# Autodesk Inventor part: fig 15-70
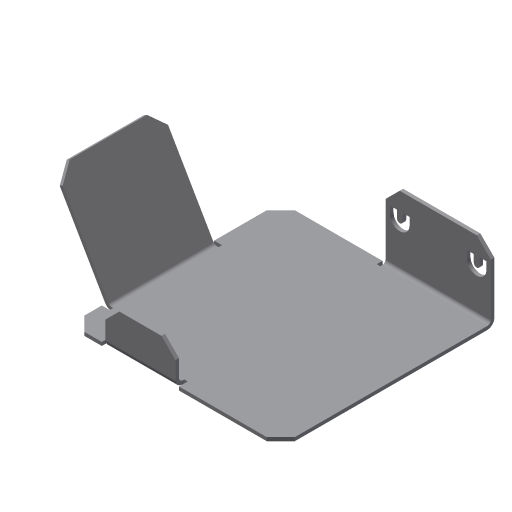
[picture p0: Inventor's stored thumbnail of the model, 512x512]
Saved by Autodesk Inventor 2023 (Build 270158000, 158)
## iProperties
Created: 2002-04
Part Number: fig 15-70
Document SubType Name: Sheet Metal
Density: 1 g/cm^3
Sheet Metal Rule: Default
Material: Generic
Appearance: Default
Control State: 0
Master: False
Checked Out: False
Shininess: 77.0
Angle Display Precision: 2
Document Length Units: 11269
Document Angle Units: 11279
Document Time Units: 11290
Document Mass Units: 11283
Document Length Units Precision: 3
Document Angle Units Precision: 2
Density: 0.0
Volumn: 0.0
Area: 0.0
PropertySet Name: Model Information
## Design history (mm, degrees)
node "Face1"
  sketch "Sketch1"
    geometry: L1 (12.647, 25.882)-(12.647, -14.118); L2 (12.647, -14.118)-(-17.353, -14.118); L3 (-17.353, -14.118)-(-17.353, 15.882); L4 (-17.353, 15.882)-(-2.353, 15.882); L5 (-2.353, 15.882)-(-2.353, 25.882); L6 (-2.353, 25.882)-(12.647, 25.882); 1 further point
    constraints: 12 end point, 4 parallel, 1 perpendicular
    dimensions: "d5" = 30 distance of L2.end L3.end; "d6" = 10 distance of L4.end L5.end; "d7" = 15 distance of L3.end L4.end; "d25" = 15 distance of L5.end L1.start
sketch "Sketch3"
  geometry: L1 (10, -15)-(10, 0)
  constraints: 2 end point
feature "Fold3" sketch "Sketch3" dims "d26" = 0.5 (= BendRadius), "d27" = 90 deg, "d28" = 0.5 (= BendRadius), "d96" = 0.5 (= BendReliefWidth), "d97" = 0.25 (= BendReliefDepth), "d98" = 1 (= MinimumRemnant), "d119" = 0.5 (= Thickness), "SeamGap" = 0.01
node "Flange2"
sketch "Sketch6"
  geometry: L1 (-6.914, 3.413)-(-5.843, 3.413); L2 (-5.843, 0.624)-(-6.914, 0.624); L3 (-6.914, 2.432)-(-5.843, 2.432); L4 (-5.843, 1.605)-(-6.914, 1.605); L5 (-6.914, 0.624)-(-6.914, 1.605); L6 (-6.914, 2.432)-(-6.914, 3.413); L7 (-6.914, 12.568)-(-6.914, 11.587); L8 (-6.914, 14.376)-(-6.914, 13.395); L9 (-6.914, 11.587)-(-5.843, 11.587); L10 (-5.843, 14.376)-(-6.914, 14.376); L11 (-6.914, 12.568)-(-5.843, 12.568); L12 (-5.843, 13.395)-(-6.914, 13.395); A1 r 1.394 centre (-5.843, 2.018) between (-5.843, 0.624) and (-5.843, 3.413); A2 r 0.413 centre (-5.843, 2.018) between (-5.843, 1.605) and (-5.843, 2.432); A3 r 1.394 centre (-5.843, 12.982) between (-5.843, 11.587) and (-5.843, 14.376); A4 r 0.413 centre (-5.843, 12.982) between (-5.843, 12.568) and (-5.843, 13.395)
  constraints: 24 end point, 8 point on circle, 4 centre point, 3 equal length, 1 perpendicular
cut "Cut1" sketch "Sketch6" dims "d49" = 0.5 (= Thickness), "d50" = 0
node "Flange3"
feature "Corner Chamfer3" dims "d107" = 2, "d108" = 6, angle "d109" = 45 deg
feature "Corner Chamfer4" dims "d110" = 2, "d111" = 6, angle "d112" = 45 deg
feature "Corner Chamfer5" dims "d113" = 2, "d114" = 6, angle "d115" = 45 deg
feature "Corner Chamfer6" dims "d116" = 2, "d117" = 6, angle "d118" = 45 deg
body "Solid1"
face "Plate1" dims "d119" = 0.5 (= Thickness)
sketch "Sketch5"
  geometry: L1 (20, 0)-(5, 0); L2 (5, 0)-(5, 15); L3 (5, 15)-(20, 15); L4 (20, 15)-(20, 0)
  constraints: 8 end point
face "Plate6" dims "d35" = 10, "d36" = 5, "d38" = 15, "d39" = 60 deg, "d40" = 0.5 (= BendRadius), "d119" = 0.5 (= Thickness), "MinimumRemnant" = 1 (= 2 x Thickness), "BendReliefWidth" = 0.5 (= Thickness)
bend "Bend5" dims "d38" = 15, "d39" = 60 deg, "d40" = 0.5 (= BendRadius), "d99" = 0.5 (= BendReliefWidth), "d100" = 0.25 (= BendReliefDepth), "d101" = 1 (= MinimumRemnant), "d119" = 0.5 (= Thickness), "SeamGap" = 0.01, "MinimumRemnant" = 1 (= 2 x Thickness), "BendReliefWidth" = 0.5 (= Thickness), "TransitionRadius" = 0.5 (= BendRadius)
sketch "Sketch7"
  geometry: L1 (25, 0)-(15, 0); L2 (15, 0)-(15, 5); L3 (15, 5)-(25, 5); L4 (25, 5)-(25, 0)
  constraints: 8 end point
face "Plate7" dims "d57" = 5, "d58" = 10, "d60" = 5, "d61" = 90 deg, "d62" = 0.5 (= BendRadius), "d119" = 0.5 (= Thickness), "MinimumRemnant" = 1 (= 2 x Thickness), "BendReliefWidth" = 0.5 (= Thickness)
bend "Bend7" dims "d59" = 0.5 (= BendRadius), "d60" = 5, "d61" = 90 deg, "d62" = 0.5 (= BendRadius), "d102" = 0.5 (= BendReliefWidth), "d103" = 0.25 (= BendReliefDepth), "d104" = 1 (= MinimumRemnant), "d119" = 0.5 (= Thickness), "SeamGap" = 0.01, "MinimumRemnant" = 1 (= 2 x Thickness), "BendReliefWidth" = 0.5 (= Thickness)
other parameters: "Thickness" = 0.5, "BendRadius" = 0.5 (= Thickness), "BendReliefDepth" = 0.25 (= 0.5 x Thickness), "CornerReliefSize" = 2 (= 4 x Thickness), "d0" = 0.5 (= BendRadius), "d13" = 0.5 (= BendRadius), "d31" = 0.5 (= BendRadius), "d37" = 0.5 (= BendRadius), "JacobiRadiusSize" = 0.5 (= Thickness), "GapSize" = 0.5 (= Thickness)
